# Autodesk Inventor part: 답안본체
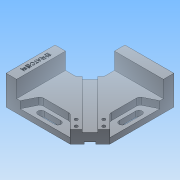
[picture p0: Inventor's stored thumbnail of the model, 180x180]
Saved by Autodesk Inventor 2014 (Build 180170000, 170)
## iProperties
Created: 2019-04
Part Number: 답안본체
Material: 일반
Document SubType Name: Modeling
Designer: net
Density: 1 g/cm^3
Appearance: 기본값
Author: net
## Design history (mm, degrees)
sketch "스케치1"
  geometry: L1 (-60, -60)-(60, -60); L2 (60, -60)-(60, 60); L3 (60, 60)-(-60, 60); L4 (-60, 60)-(-60, -60); L5 (-60, -60)-(60, 60); L6 (60, -60)-(-60, 60); 1 further point
  constraints: 12 end point, 2 midpoint, 2 parallel, 1 horizontal, 1 perpendicular
  dimensions: "d0" = 120 distance of L2.end L3.end; "d1" = 120 distance of L3.end L1.start
extrude "돌출1" new body sketch "스케치1" stored distance "d2" = 42; taper "d3" = 0 deg
sketch "스케치2"
  geometry: L1 (-60, -60)-(60, -60) reference; L2 (60, -60)-(60, 60) reference; L3 (31.716, -60)-(60, -31.716); 1 further point
  constraints: 2 end point, 2 point on line
  dimensions: "d7" = 20 distance from line of L1.end L3
extrude "돌출2" cut sketch "스케치2" distance "d8" = 42; taper "d9" = 0 deg
sketch "스케치3"
  geometry: L1 (31.716, -60)-(60, -31.716) reference; L2 (60, 60)-(-60, 60) reference; L3 (-60, 60)-(-60, -60) reference; L4 (-60, 10)-(-10, 10); L5 (-10, 10)-(-10, 60); L6 (-10, 29.806)-(-29.806, 10); 1 further point
  constraints: 6 end point, 4 point on line, 2 perpendicular, 1 parallel
  dimensions: "d10" = 50 distance of L4.end L5.end; "d11" = 50 distance of L4.start L4.end; "d12" = 93 distance between parallel lines of L1 L6
extrude "돌출3" cut sketch "스케치3" distance "d13" = 42; taper "d14" = 0 deg
sketch "스케치4"
  geometry: L1 (-10, 60)-(-10, 29.806) reference; L2 (-10, 29.806)-(-29.806, 10) reference; L3 (-29.806, 10)-(-60, 10) reference; L4 (-60, 10)-(-60, -60) reference; L5 (-60, -60)-(31.716, -60) reference; L6 (31.716, -60)-(60, -31.716) reference; L7 (60, -31.716)-(60, 60) reference; L8 (60, 60)-(-10, 60) reference; L9 (-45, 10)-(-45, -60); L10 (-10, 45)-(60, 45); 1 further point
  constraints: 4 end point, 4 point on line, 2 perpendicular
  dimensions: "d15" = 15 distance between parallel lines of L4 L9; "d16" = 15 distance between parallel lines of L8 L10
extrude "돌출4" cut sketch "스케치4" distance "d17" = 24; taper "d18" = 0 deg
sketch "스케치5"
  geometry: L1 (-29.806, 10)-(-10, 29.806) reference; L2 (31.716, -60)-(-45, -60) reference; L3 (60, -31.716)-(31.716, -60) reference; L4 (-10, 29.806)-(-10, 45) reference; L5 (-40, -60)-(-30, -40); L6 (-30, -40)-(11.716, -40); L7 (11.716, -40)-(31.716, -60); L8 (-60, 10)-(-60, -60) reference; L9 (-19.903, 19.903)-(45.858, -45.858); 1 further point
  constraints: 8 end point, 2 midpoint, 2 point on line, 1 parallel, 1 perpendicular
  dimensions: "d19" = 20 distance from line of L5.start L8; "d20" = 30 horizontal distance of L8.end L5.end; "d21" = 20 distance between parallel lines of L9 L7; "d22" = 20 distance between parallel lines of L2 L6
extrude "돌출5" cut sketch "스케치5" distance "d23" = 10; taper "d24" = 0 deg
sketch "스케치6"
  geometry: L1 (60, -31.716)-(31.716, -60) reference; L2 (60, 45)-(60, -31.716) reference; L3 (-29.806, 10)-(-10, 29.806) reference; L4 (-30, -40)-(11.716, -40) reference; L5 (60, 40)-(40, 30); L6 (40, 30)-(40, -11.716); L7 (40, -11.716)-(60, -31.716); L8 (-19.903, 19.903)-(45.858, -45.858); L9 (60, 60)-(-10, 60) reference; 1 further point
  constraints: 8 end point, 2 midpoint, 2 perpendicular, 1 parallel, 1 point on line
  dimensions: "d25" = 20 distance from line of L9 L5.start; "d26" = 30 distance from line of L9 L5.end; "d27" = 20 distance between parallel lines of L2 L6
extrude "돌출6" cut sketch "스케치6" distance "d28" = 10; taper "d29" = 0 deg
fillet "모깎기1" dims "d30" = 5
sketch "스케치7"
  geometry: L1 (-26.91, -40)-(9.645, -40) reference; L2 (31.716, -60)-(-40, -60) reference; L3 (-20, -50)-(4, -50); L4 (-20, -54.5)-(4, -54.5); L5 (4, -45.5)-(-20, -45.5); L6 (-60, 10)-(-60, -60) reference; A1 r 4.5 centre (-20, -50) between (-20, -45.5) and (-20, -54.5); A2 r 4.5 centre (4, -50) between (4, -54.5) and (4, -45.5); 2 further points
  constraints: 8 end point, 4 point on circle, 4 tangent, 2 centre point, 2 parallel, 1 midpoint
  dimensions: "d31" = 10 distance from line of L2 point (-8, -50); "d32" = 9 distance between parallel lines of L4 L5; "d33" = 40 distance from line of L6 L3.start; "d34" = 24 distance of L4.start L4.end
extrude "돌출7" cut sketch "스케치7" distance "d35" = 10; taper "d36" = 0 deg
sketch "스케치8"
  geometry: L1 (60, 40)-(60, -31.716) reference; L2 (40, -9.645)-(40, 26.91) reference; L3 (50, 20)-(50, -4); L4 (45.5, 20)-(45.5, -4); L5 (54.5, -4)-(54.5, 20); L6 (60, 60)-(-10, 60) reference; A1 r 4.5 centre (50, 20) between (54.5, 20) and (45.5, 20); A2 r 4.5 centre (50, -4) between (45.5, -4) and (54.5, -4); 2 further points
  constraints: 8 end point, 4 point on circle, 4 tangent, 2 centre point, 2 parallel, 1 midpoint
  dimensions: "d37" = 9 distance between parallel lines of L5 L4; "d38" = 10 distance from line of L1 point (50, 8); "d39" = 24 distance of L4.start L4.end; "d40" = 40 distance from line of L6 L3.start
extrude "돌출8" cut sketch "스케치8" distance "d41" = 10; taper "d42" = 0 deg
sketch "스케치9"
  geometry: L1 (-40, 0)-(0, 0) reference; L2 (-40, 18)-(0, 18) reference; L3 (-14, 15)-(-26, 15); L4 (-26, 15)-(-26, 18); L5 (-26, 18)-(-14, 18); L6 (-14, 18)-(-14, 15); L7 (-14, 15)-(-26, 18); L8 (-26, 15)-(-14, 18); L9 (-12, 3.5)-(-28, 3.5); L10 (-28, 3.5)-(-28, 0); L11 (-28, 0)-(-12, 0); L12 (-12, 0)-(-12, 3.5); L13 (-12, 3.5)-(-28, 0); L14 (-28, 3.5)-(-12, 0); 5 further points
  constraints: 24 end point, 6 midpoint, 4 parallel, 2 horizontal, 2 perpendicular, 2 point on line, 2 vertical alignment
  dimensions: "d43" = 16 distance of L9.start L9.end; "d44" = 3.5 distance of L11.end L9.start; "d45" = 12 distance of L3.start L3.end; "d46" = 3 distance of L3.end L4.end
extrude "돌출9" cut sketch "스케치9" stored distance "d47" = 10; taper "d48" = 0 deg
sketch "스케치10"
  geometry: L1 (40.201, -51.515)-(-25.56, 14.246) reference; L2 (40.201, -51.515)-(31.716, -60) reference; L3 (9.645, -40)-(-26.91, -40) reference; L4 (-31.382, -42.764)-(-40, -60) reference; L5 (-40, -60)-(-45, -60) reference; L6 (-45, -60)-(-60, -60) reference; L7 (-60, -60)-(-60, 10) reference; L8 (-60, 10)-(-45, 10) reference; L9 (-45, 10)-(-29.806, 10) reference; L10 (-29.806, 10)-(-25.56, 14.246) reference; L11 (-25.56, 14.246)-(40.201, -51.515) reference; L12 (40.201, -51.515)-(31.716, -60) reference; L13 (31.716, -60)-(13.18, -41.464) reference; L14 (-45, 10)-(-45, -60) reference; L15 (60, 45)-(-10, 45) reference; L16 (-10, 29.806)-(-10, 45) reference; L17 (-14.246, 25.56)-(-10, 29.806) reference; L18 (51.515, -40.201)-(-14.246, 25.56) reference; L19 (60, -31.716)-(51.515, -40.201) reference; L20 (41.464, -13.18)-(60, -31.716) reference; L21 (40, 26.91)-(40, -9.645) reference; L22 (60, 40)-(42.764, 31.382) reference; L23 (60, 45)-(60, 40) reference; L24 (60, 60)-(60, 45) reference; L25 (-10, 60)-(60, 60) reference; L26 (-10, 45)-(-10, 60) reference; L27 (9.645, -40)-(-26.91, -40) reference; L28 (-31.382, -42.764)-(-40, -60) reference; L29 (-40, -60)-(-45, -60) reference; L30 (-45, -60)-(-60, -60) reference; L31 (-60, -60)-(-60, 10) reference; L32 (-60, 10)-(-45, 10) reference; L33 (-45, 10)-(-29.806, 10) reference; L34 (-29.806, 10)-(-25.56, 14.246) reference; L35 (-25.56, 14.246)-(40.201, -51.515) reference; L36 (40.201, -51.515)-(31.716, -60) reference; L37 (31.716, -60)-(13.18, -41.464) reference; L38 (-45, 10)-(-45, -60) reference; L39 (60, 45)-(-10, 45) reference; L40 (-10, 29.806)-(-10, 45) reference; L41 (-14.246, 25.56)-(-10, 29.806) reference; L42 (51.515, -40.201)-(-14.246, 25.56) reference; L43 (60, -31.716)-(51.515, -40.201) reference; L44 (41.464, -13.18)-(60, -31.716) reference; L45 (40, 26.91)-(40, -9.645) reference; L46 (60, 40)-(42.764, 31.382) reference; L47 (60, 45)-(60, 40) reference; L48 (60, 60)-(60, 45) reference; L49 (-10, 60)-(60, 60) reference; L50 (-10, 45)-(-10, 60) reference; C1 r 2.25 at (31.716, -51.515); C2 r 2.25 at (23.23, -43.029); C3 r 2.25 at (43.029, -23.23); C4 r 2.25 at (51.515, -31.716); A1 r 5 centre (9.645, -45) between (13.18, -41.464) and (9.645, -40) reference; A2 r 5 centre (-26.91, -45) between (-26.91, -40) and (-31.382, -42.764) reference; A3 r 5 centre (45, -9.645) between (40, -9.645) and (41.464, -13.18) reference; A4 r 5 centre (45, 26.91) between (42.764, 31.382) and (40, 26.91) reference; A5 r 5 centre (9.645, -45) between (13.18, -41.464) and (9.645, -40) reference; A6 r 5 centre (-26.91, -45) between (-26.91, -40) and (-31.382, -42.764) reference; A7 r 5 centre (45, -9.645) between (40, -9.645) and (41.464, -13.18) reference; A8 r 5 centre (45, 26.91) between (42.764, 31.382) and (40, 26.91) reference; 1 further point
  constraints: 4 centre point
  dimensions: "d49" = 4.5 diameter of C1; "d50" = 4.5 diameter of C2; "d51" = 4.5 diameter of C3; "d52" = 4.5 diameter of C4; "d53" = 6 distance from line of L2 C1.centre; "d54" = 6 distance from line of L1 C1.centre; "d55" = 6 distance from line of L43 C4.centre; "d56" = 6 distance from line of L42 C4.centre; "d57" = 18 distance from line of L2 C2.centre; "d58" = 18 distance from line of L19 C3.centre; "d59" = 6 distance from line of L20 C3.centre; "d60" = 6 distance from line of L1 C2.centre
extrude "돌출10" cut sketch "스케치10" stored distance "d61" = 10; taper "d62" = 0 deg
sketch "스케치11"
  geometry: L1 (15.66, 24.146)-(-50.101, -41.615) reference; L2 (-50.101, -41.615)-(-60, -31.716) reference; L3 (-60, -31.716)-(-60, 60) reference; L4 (-60, 60)-(10, 60) reference; L5 (10, 60)-(10, 29.806) reference; L6 (10, 29.806)-(15.66, 24.146) reference; L7 (-54.5, 20)-(-54.5, -4) reference; L8 (-45.5, -4)-(-45.5, 20) reference; L9 (20, -45.5)-(-4, -45.5) reference; L10 (-4, -54.5)-(20, -54.5) reference; L11 (60, -60)-(-31.716, -60) reference; L12 (-31.716, -60)-(-41.615, -50.101) reference; L13 (-41.615, -50.101)-(24.146, 15.66) reference; L14 (24.146, 15.66)-(29.806, 10) reference; L15 (29.806, 10)-(60, 10) reference; L16 (60, 10)-(60, -60) reference; C1 r 2.25 at (-31.716, -51.515) reference; C2 r 2.25 at (-23.23, -43.029) reference; C3 r 2.25 at (-31.716, -51.515) reference; C4 r 2.25 at (-43.029, -23.23) reference; C5 r 2.25 at (-51.515, -31.716) reference; C6 r 2.25 at (-23.23, -43.029) reference; C7 r 4 at (-43.029, -23.23); C8 r 4 at (-51.515, -31.716); C9 r 4 at (-23.23, -43.029); C10 r 4 at (-31.716, -51.515); A1 r 4.5 centre (-50, 20) between (-45.5, 20) and (-54.5, 20) reference; A2 r 4.5 centre (-50, -4) between (-54.5, -4) and (-45.5, -4) reference; A3 r 4.5 centre (20, -50) between (20, -54.5) and (20, -45.5) reference; A4 r 4.5 centre (-4, -50) between (-4, -45.5) and (-4, -54.5) reference; 1 further point
  constraints: 4 centre point, 4 coincident
  dimensions: "d63" = 8 diameter of C7; "d64" = 8 diameter of C8; "d65" = 8 diameter of C9; "d66" = 8 diameter of C10
extrude "돌출11" cut sketch "스케치11" distance "d67" = 10; taper "d68" = 0 deg
fillet "모깎기2" dims "d69" = 5
sketch "스케치12"
  geometry: L1 (-60, 10)-(-60, -60) reference; 3 further points
  constraints: 1 other
  dimensions: "d70" = 7.5 distance from line of L1 point (-52.5, -25); "d71" = 35 vertical distance of point (-45, 10) point (-52.5, -25)
feature "엠보싱1" sketch "스케치12" dims "d0" = 120, "d1" = 120, "d10" = 50, "d11" = 50, "d12" = 93, "d72" = 0.5, "d73" = 0
node "솔리드1"
node "절단 모서리 투영1"
node "절단 모서리 투영2"
node "절단 모서리 투영3"
